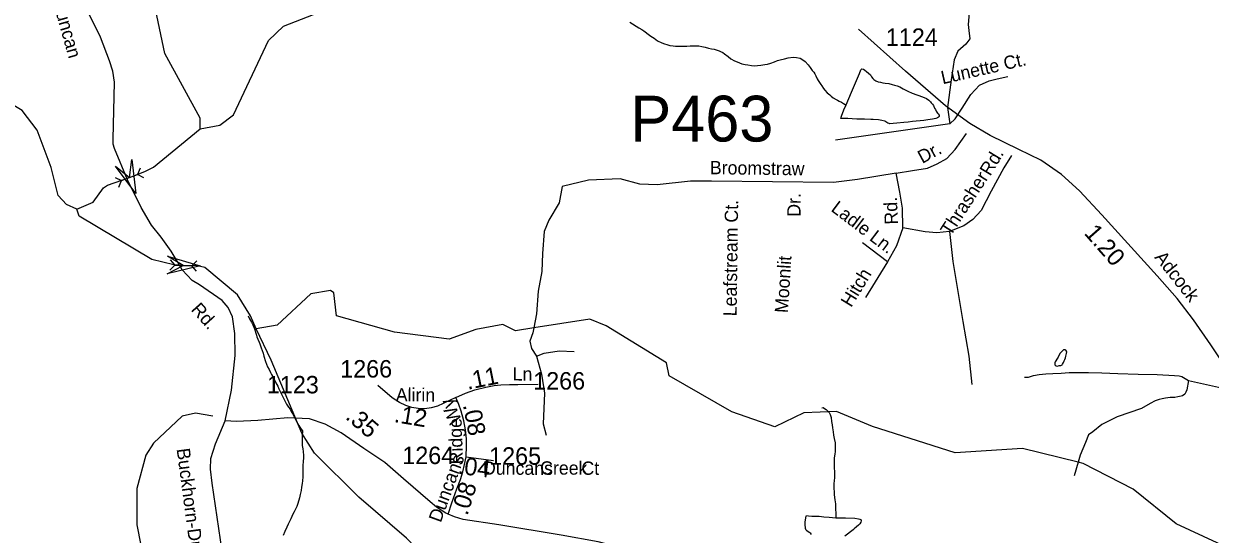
# Model space of a CAD drawing. Extents: x 2001466 to 2224147, y 644118 to 847247.
# Drawn here: x 2037525 to 2046028, y 669371 to 673026 of the extents above; entities that cross this region are included whole.
import ezdxf

# ---------------------------------------------------------------- set-up
doc = ezdxf.new("R2010")
doc.units = 0
for name, color, linetype in [('Exist Hydrographic Creek Single Shore', 7, 'Continuous'), ('Exist Hydrographic Misc Water Feature', 7, 'Continuous'), ('Exist Road Non-System Type 51', 7, 'Continuous'), ('Exist Road Non-System Type 51 Label', 7, 'Continuous'), ('Exist Road Secondary Mileage Hundredths English Label', 7, 'Continuous'), ('Exist Road Secondary Structure Pipe Attributed CELL', 7, 'Continuous'), ('Exist Road Secondary Structure Pipe CELL', 7, 'Continuous'), ('Exist Road Secondary Structure Pipe Number Label', 7, 'Continuous'), ('Exist Road Secondary Type 51 Attributed', 7, 'Continuous'), ('Exist Road Secondary Type 51 Label', 7, 'Continuous'), ('Exist Road Secondary Type 51 Number Label', 7, 'Continuous')]:
    doc.layers.add(name, color=color, linetype=linetype)

msp = doc.modelspace()

# ---------------------------------------------------------------- linework, layer by layer
at = {"layer": 'Exist Hydrographic Creek Single Shore'}
for points in [[(2038788.6, 672274), (2038930.7, 672300.6), (2039029.5, 672374), (2039278.6, 672907.1), (2039387.5, 673009.9), (2039645.7, 673109.6), (2040194.6, 673236.3), (2040902.7, 673569.6), (2041035.5, 673711.3), (2041110.6, 673860.7), (2041617.7, 674513.2), (2041766.5, 674605.3), (2042058.7, 674697.8), (2042616.7, 674673.3)], [(2037906.6, 671698), (2037831.6, 671732.4), (2037772.5, 671795.9), (2037722.5, 671997.1), (2037622.6, 672264.9), (2037513.6, 672404.9), (2037430.5, 672455.7), (2037236.1, 672453.3)], [(2037906.6, 671698), (2038022.5, 671748.2), (2038097, 671850.7), (2038125.6, 671871.2), (2038283.2, 671924.9), (2038393.2, 671968.8), (2038456.2, 671998.9), (2038788.6, 672274)], [(2039190.5, 670841.9), (2039149.5, 670934.6), (2039057.6, 671084.1), (2038823.4, 671280.8), (2038769.9, 671291.8), (2038668.7, 671295.5), (2038600.6, 671299.2), (2038444.5, 671338.8), (2037923.7, 671648.5), (2037906.6, 671698)]]:
    msp.add_lwpolyline(points, dxfattribs=at)
at = {"layer": 'Exist Hydrographic Misc Water Feature'}
for points in [[(2038788.6, 672274), (2038788.6, 672349.4), (2038537.6, 672813.9), (2038470.5, 673130.2), (2038211.6, 673388.1), (2038211.6, 673463.6), (2038027.6, 673723.2), (2038043.1, 674053.8)], [(2041868, 673038.1), (2041887.9, 673026.2), (2041914, 673010.2), (2041933.9, 672998.3), (2041954.2, 672986.3), (2041968.1, 672976.3), (2041978.2, 672968.3), (2042000.1, 672952.4), (2042020, 672938.4), (2042042.1, 672922.4), (2042068.2, 672904.5), (2042098.1, 672890.6), (2042116.2, 672882.6), (2042134.2, 672876.6), (2042156.1, 672870.7), (2042178.3, 672868.7), (2042196.1, 672866.7), (2042212.1, 672864.8), (2042232.2, 672864.8), (2042256.2, 672866.9), (2042276.3, 672866.9), (2042300.3, 672868.9), (2042332.3, 672869), (2042362.2, 672867.1), (2042384.2, 672863.1), (2042408.2, 672859.1), (2042432.1, 672851.2), (2042454.3, 672847.2), (2042474.2, 672843.2), (2042488.1, 672839.3), (2042508.2, 672831.3), (2042518.3, 672827.4), (2042536.1, 672819.4), (2042546.2, 672811.5), (2042572.4, 672791.4), (2042592.3, 672775.5), (2042618.3, 672761.6), (2042638.4, 672753.6), (2042672.3, 672739.6), (2042694.4, 672735.7), (2042714.3, 672731.7), (2042740.3, 672727.8), (2042760.2, 672725.8), (2042784.4, 672727.9), (2042808.4, 672730), (2042836.3, 672734), (2042854.3, 672736), (2042878.3, 672744.1), (2042904.4, 672754.1), (2042926.3, 672762.1), (2042946.2, 672768.1), (2042976.1, 672776.2), (2043004.2, 672782.2), (2043038.3, 672786.3)], [(2043038.3, 672786.3), (2043064.1, 672784.4), (2043090.2, 672780.4), (2043108.2, 672768.5), (2043126.2, 672756.5), (2043146.3, 672732.5), (2043160.3, 672712.6), (2043174.2, 672692.6), (2043186.3, 672678.6), (2043194.5, 672666.6), (2043202.5, 672652.6), (2043212.4, 672632.7), (2043218.5, 672620.7), (2043228.4, 672606.7), (2043238.6, 672590.8), (2043244.6, 672580.8), (2043256.7, 672562.8), (2043266.5, 672550.8), (2043282.5, 672532.8), (2043292.7, 672524.9), (2043302.6, 672516.9), (2043312.6, 672506.9), (2043326.8, 672496.9), (2043346.7, 672485), (2043356.7, 672479), (2043368.6, 672473), (2043384.6, 672465), (2043400.6, 672455.1), (2043412.9, 672449.1), (2043418.9, 672445.1)], [(2043418.9, 672445.1), (2043456.6, 672537.2), (2043514.4, 672669.2), (2043524.3, 672695.3), (2043532.2, 672703.3), (2043542.3, 672701.3), (2043552.3, 672693.4), (2043564.2, 672683.4), (2043578.4, 672671.4), (2043592.3, 672659.4), (2043600.3, 672647.4), (2043610.4, 672635.4), (2043618.4, 672627.5), (2043632.5, 672617.5), (2043648.5, 672611.5), (2043664.5, 672607.5), (2043682.3, 672603.6), (2043698.3, 672601.6), (2043724.4, 672597.6), (2043748.4, 672591.7), (2043766.4, 672587.7), (2043784.5, 672581.8), (2043802.5, 672573.8), (2043828.3, 672559.9), (2043860.5, 672543.9), (2043892.5, 672530), (2043924.5, 672518), (2043940.5, 672512), (2043958.6, 672506.1), (2043978.6, 672498.1), (2043994.6, 672490.1), (2044010.6, 672480.2), (2044022.5, 672468.2), (2044028.7, 672460.2), (2044038.7, 672450.3), (2044044.7, 672440.3), (2044052.7, 672422.3), (2044058.6, 672412.3), (2044064.8, 672400.3), (2044072.8, 672386.3), (2044078.7, 672380.3), (2044084.9, 672372.3), (2044084.9, 672362.3), (2044080.8, 672358.3), (2044072.8, 672352.4), (2044060.9, 672348.3), (2044038.7, 672344.3), (2044004.9, 672338.2), (2043974.8, 672334.2), (2043895, 672326.1), (2043863, 672322), (2043832.9, 672319.9), (2043781, 672313.8), (2043754.9, 672311.8), (2043733, 672309.7), (2043726.8, 672311.7), (2043718.8, 672315.6), (2043696.9, 672327.6), (2043675, 672333.6), (2043651, 672337.5), (2043612.8, 672341.5), (2043596.8, 672341.5), (2043550.9, 672343.3), (2043531, 672343.3), (2043494.9, 672343.3), (2043460.9, 672345.2), (2043431, 672347.2), (2043412.9, 672347.1), (2043394.9, 672347.1), (2043380.9, 672347), (2043385, 672365), (2043402.9, 672409.1), (2043418.9, 672445.1)], [(2041180.7, 670847.9), (2041049.5, 670827.1), (2040957.6, 670871.6), (2040765.5, 670836.1), (2040574.6, 670767.9), (2040182.5, 670818.5), (2039765.6, 670935.2), (2039748.6, 671099.6), (2039723.6, 671116.5), (2039582.5, 671093.1), (2039340.6, 670868.4), (2039190.5, 670841.9)], [(2039134.3, 670935.4), (2039144.3, 670913.3), (2039158.3, 670889.4), (2039166.5, 670871.4), (2039174.5, 670853.5), (2039182.5, 670835.5), (2039188.4, 670811.5), (2039192.5, 670795.5), (2039196.6, 670783.5), (2039202.6, 670767.6), (2039212.6, 670745.6), (2039216.7, 670733.6), (2039226.8, 670705.6), (2039234.8, 670687.6), (2039240.7, 670667.6), (2039246.9, 670645.6), (2039258.8, 670607.7), (2039264.9, 670589.7), (2039272.9, 670569.7), (2039283, 670549.7), (2039293, 670529.7), (2039301, 670513.8), (2039314.9, 670489.8), (2039322.9, 670475.8), (2039333, 670455.8), (2039345.1, 670431.9), (2039353.1, 670411.9), (2039365.2, 670387.8), (2039375.2, 670368), (2039385.3, 670349.9), (2039409.5, 670302), (2039423.4, 670280), (2039433.5, 670266), (2039445.4, 670246.1), (2039453.6, 670232.1), (2039475.5, 670188.1), (2039495.6, 670150.2), (2039503.6, 670138.2), (2039513.6, 670122.2), (2039523.7, 670110.3)], [(2045081.2, 669887), (2044683.4, 669985.5), (2044200.5, 669952.7), (2043608.5, 670141.9), (2043349.5, 670248.8), (2043116.4, 670240.5), (2042908.5, 670139.7), (2042599.5, 670247.7), (2042149.6, 670506.2), (2042132.6, 670598.4), (2041698.5, 670863.1), (2041582.6, 670911.4), (2041180.7, 670847.9)], [(2041120.4, 668328.9), (2040778.4, 668654), (2040469.6, 669136.1), (2040268.4, 669343.6), (2039926.6, 669635.9), (2039609.6, 669950.8), (2039517.5, 670093.8), (2039299.6, 670616.5), (2039190.5, 670841.9)], [(2044937.7, 670638.3), (2044929.7, 670624.2), (2044921.7, 670612.2), (2044917.8, 670606.2), (2044913.9, 670598.2), (2044913.9, 670592.2), (2044913.9, 670586.2), (2044915.9, 670582.2), (2044923.9, 670576.2), (2044933.8, 670574.2), (2044945.9, 670578.2), (2044957.8, 670580.3), (2044966, 670584.3), (2044969.9, 670588.3), (2044975.8, 670600.3), (2044981.8, 670612.3), (2044985.7, 670622.4), (2044989.8, 670634.4), (2044993.7, 670646.4), (2044995.7, 670656.4), (2044997.8, 670664.4), (2044999.6, 670676.4), (2044997.6, 670682.4), (2044993.7, 670688.4), (2044989.6, 670692.3), (2044981.6, 670692.3), (2044975.6, 670690.3), (2044969.7, 670684.3), (2044963.7, 670680.3), (2044949.8, 670664.3), (2044937.7, 670638.3)], [(2043244.8, 670277.2), (2043254.5, 670278.1), (2043264.7, 670271.2), (2043276.8, 670263.2), (2043286.8, 670253.2), (2043296.8, 670243.3), (2043304.8, 670227.3), (2043310.8, 670207.2), (2043314.9, 670179.3), (2043318.8, 670155.3), (2043321, 670133.3), (2043324.9, 670105.3), (2043329, 670079.3), (2043333.1, 670055.4), (2043339.1, 670025.4), (2043339.3, 670005.4), (2043339.3, 669963.4), (2043337.4, 669945.4), (2043333.3, 669917.4), (2043333.3, 669891.4), (2043333.6, 669865.4), (2043333.6, 669841.4), (2043335.4, 669823.4), (2043335.6, 669801.4), (2043335.6, 669777.4), (2043333.6, 669753.4), (2043331.7, 669735.4), (2043331.7, 669719.4), (2043331.7, 669699.4), (2043331.9, 669673.4), (2043333.8, 669655.5), (2043335.8, 669633.5), (2043337.9, 669617.5), (2043342, 669589.5), (2043342, 669571.5), (2043342, 669551.4), (2043344, 669521.5), (2043346.1, 669503.5), (2043346.1, 669489.5)], [(2039523.7, 670110.3), (2039519.8, 670072.3), (2039519.8, 670048.2), (2039520, 670026.2), (2039521.8, 670006.2), (2039523.9, 669994.3), (2039525.9, 669982.3), (2039528, 669964.3), (2039530, 669934.3), (2039530, 669920.3), (2039528.2, 669888.3), (2039526.1, 669866.3), (2039526.1, 669850.3), (2039526.1, 669838.3), (2039526.4, 669820.3), (2039526.4, 669800.3), (2039524.3, 669782.3), (2039522.5, 669754.3), (2039520.4, 669734.3), (2039516.3, 669708.3), (2039512.6, 669684.3), (2039506.5, 669654.3), (2039500.5, 669632.2), (2039496.6, 669614.2), (2039486.6, 669584.2), (2039482.7, 669570.3), (2039474.7, 669554.3), (2039462.8, 669530.3), (2039454.8, 669514.2), (2039438.8, 669480.2), (2039430.8, 669462.2), (2039421, 669442.2), (2039410.9, 669422.1), (2039397, 669390.1), (2039385.1, 669362.1)], [(2046476.4, 668863.1), (2046176.4, 669262.9), (2045784.5, 669444.8), (2045475.5, 669693.8), (2045116.5, 669878.3), (2045081.2, 669887)], [(2043170.3, 669369.2), (2043166.4, 669375.1), (2043158.4, 669381.1), (2043146.3, 669389.1), (2043138.3, 669395.1), (2043132.4, 669401.1), (2043128.3, 669411.1), (2043126.5, 669421.1), (2043124.2, 669433.1), (2043124.2, 669445.1), (2043126.2, 669459.1), (2043128.3, 669471.1), (2043130.1, 669489.1), (2043132.2, 669501.1), (2043134, 669505.1), (2043150, 669503.2), (2043172.2, 669501.2), (2043200.1, 669501.2), (2043226.1, 669499.3), (2043258.1, 669495.4), (2043298.1, 669493.4), (2043346.1, 669489.5)], [(2043346.1, 669489.5), (2043386, 669487.6), (2043414.1, 669487.6), (2043480.2, 669485.7), (2043508.1, 669481.8), (2043518.1, 669479.8), (2043526.1, 669473.8), (2043526.1, 669467.8), (2043524, 669457.8), (2043516.3, 669445.8), (2043508.3, 669435.8), (2043492.3, 669423.8), (2043476.3, 669409.7), (2043468.3, 669401.7), (2043450.4, 669387.7), (2043428.3, 669371.7), (2043408.4, 669357.7)]]:
    msp.add_lwpolyline(points, dxfattribs=at)
at = {"layer": 'Exist Road Non-System Type 51'}
for p, q in [((2044161.3, 672309.9), (2043342.9, 672192.5)), ((2043714.6, 671321.8), (2043536.4, 671456.8)), ((2043714.6, 671321.8), (2043558, 671065.2)), ((2045871.9, 670471.2), (2046173, 670406.1)), ((2045081.2, 669887), (2045052.5, 669790.2))]:
    msp.add_line(p, q, dxfattribs=at)
for points in [[(2044319.9, 673656.2), (2044312, 673281.1), (2044304.1, 673163.5), (2044298.8, 673076.4), (2044293.5, 673020.9), (2044298.8, 672978.6), (2044304.1, 672917.9), (2044277.7, 672880.9), (2044219.6, 672830.7), (2044193.2, 672767.3), (2044172.1, 672624.7), (2044145.7, 672426.6), (2044161.3, 672309.9)], [(2044161.3, 672309.9), (2044201.1, 672346), (2044251.3, 672422.6), (2044312, 672520.4), (2044375.4, 672586.4), (2044444, 672618.1), (2044502.1, 672631.3), (2044578.7, 672649.8)], [(2043776.7, 671956.6), (2043895.5, 671975.5), (2044000.8, 671991.7), (2044071, 672024.1), (2044141.2, 672061.9), (2044200.6, 672126.7), (2044282.1, 672240.4)], [(2044602.9, 672083.5), (2044548.9, 671994.4), (2044457.1, 671826.9), (2044386.9, 671689.1), (2044327.5, 671624.3), (2044262.7, 671578.4), (2044160.1, 671537.9)], [(2043776.7, 671956.6), (2043501.3, 671910.6), (2043328.5, 671889), (2042453.7, 671899.8), (2042302.5, 671899.8), (2042064.9, 671872.8), (2041940.7, 671878.2), (2041800.3, 671916), (2041573.5, 671905.2), (2041384.5, 671862), (2041362.9, 671743.2), (2041287.3, 671618.9), (2041254.9, 671537.9), (2041244.1, 671381.2), (2041238.7, 671251.5), (2041211.7, 671111.1), (2041200.9, 670949), (2041180.7, 670847.9)], [(2043825.3, 671564.9), (2043822.6, 671705.3), (2043803.7, 671821.5), (2043776.7, 671956.6)], [(2043825.3, 671564.9), (2043779.4, 671435.2), (2043714.6, 671321.8)], [(2044160.1, 671537.9), (2044068.3, 671529.8), (2043984.6, 671535.2), (2043825.3, 671564.9)], [(2044160.1, 671537.9), (2044184.4, 671324.5), (2044254.6, 670895), (2044297.8, 670646.5), (2044319.4, 670443.9)], [(2041180.7, 670847.9), (2041173.9, 670813.9), (2041152.3, 670754.5), (2041163.1, 670700.5), (2041200.9, 670646.5)], [(2041200.9, 670646.5), (2041254.9, 670668.1), (2041362.9, 670684.3), (2041470.9, 670678.9)], [(2041200.9, 670646.5), (2041236, 670516.8), (2041257.6, 670381.8), (2041246.8, 670160.3), (2041268.4, 670079.2)], [(2044696.4, 670495), (2044710.4, 670494.8), (2044726.4, 670496.4), (2044760.6, 670507.7), (2044802.8, 670514.9), (2044848.9, 670520), (2044898.9, 670520.9), (2044959, 670523.7), (2045017.1, 670528.5), (2045061.1, 670529.6), (2045155.1, 670529.7), (2045251, 670525.8), (2045366.9, 670521.4), (2045510.8, 670516.5), (2045648.8, 670513.7), (2045772.6, 670507.2), (2045804.6, 670504.5), (2045824.5, 670500.1), (2045871.9, 670471.2)], [(2045871.9, 670471.2), (2045860.6, 670405.4), (2045854.2, 670387.5), (2045845.9, 670373.7), (2045829.7, 670362), (2045819.6, 670360.2), (2045795.5, 670354.7), (2045773.5, 670351.2), (2045741.4, 670349.8), (2045707.3, 670344.5), (2045683.2, 670341), (2045663.1, 670335.4), (2045632.9, 670326), (2045598.5, 670306.7), (2045535.8, 670272), (2045360.3, 670211.6), (2045252.3, 670157.5), (2045187.5, 670103.5), (2045155.1, 670081.9), (2045133.5, 670027.9), (2045095.7, 669936.1), (2045081.2, 669887)], [(2038881.6, 670217), (2038757.4, 670238.6), (2038660.2, 670217), (2038454.9, 670022.5), (2038400.9, 669936), (2038336.1, 669698.3), (2038336.1, 669439), (2038390.1, 669158.1), (2038428.2, 668960.1)]]:
    msp.add_lwpolyline(points, dxfattribs=at)
at = {"layer": 'Exist Road Secondary Structure Pipe Attributed CELL'}
for points in [[(2038298.9, 672053.9), (2038329.2, 671812), (2038181.9, 672006.4), (2038283.2, 671924.9)], [(2038556.5, 671361.1), (2038790.6, 671292.8), (2038553.8, 671234.9), (2038668.7, 671295.5)]]:
    msp.add_lwpolyline(points, close=True, dxfattribs=at)
at = {"layer": 'Exist Road Secondary Structure Pipe CELL'}
for p, q in [((2038359.5, 671993), (2038339.8, 671946.2)), ((2038181, 671925.8), (2038226.6, 671903.6)), ((2038206.9, 671856.8), (2038226.6, 671903.6)), ((2038226.6, 671903.6), (2038339.8, 671946.2)), ((2038385.5, 671924), (2038339.8, 671946.2)), ((2038575, 671336.3), (2038608.3, 671298)), ((2038765.5, 671328.4), (2038729.1, 671293)), ((2038571.9, 671262.6), (2038608.3, 671298)), ((2038608.3, 671298), (2038729.1, 671293)), ((2038762.5, 671254.7), (2038729.1, 671293))]:
    msp.add_line(p, q, dxfattribs=at)
at = {"layer": 'Exist Road Secondary Type 51 Attributed'}
msp.add_line((2040695.5, 669924.3), (2040892.1, 669900), dxfattribs=at)
for points in [[(2038968.1, 670183.9), (2039014.1, 670403.3), (2039040.5, 670651.7), (2039037.1, 670807.5), (2039020.5, 670926.8), (2038991.2, 670994.7), (2038947.4, 671045.4), (2038784.1, 671157), (2038732.7, 671188.2), (2038659.6, 671263.1), (2038624.7, 671325.5), (2038582.2, 671398.1), (2038510.4, 671497.2), (2038442, 671585.1), (2038367.7, 671709.6), (2038268.7, 671907.9), (2038174.7, 672133.9), (2038165.1, 672164.5), (2038165.3, 672199.3), (2038176.2, 672607.7), (2038163.6, 672685.9), (2038140.1, 672761.9), (2038075.8, 672930.3), (2037992.6, 673099.8)], [(2048069.1, 669827.3), (2047827.8, 669845.2), (2047566, 669864.2), (2047497.9, 669887.4), (2047112.6, 670048), (2046612.3, 670260.3), (2046306.7, 670400.8), (2046240.2, 670447.3), (2046147.3, 670556.1), (2046032.2, 670726.2), (2045908.2, 670906.8), (2045789.9, 671058.9), (2045648.5, 671221.6), (2045252.1, 671658.9), (2045091.1, 671829), (2044962.4, 671947.3), (2044813.5, 672048.7), (2044655.2, 672125.8), (2044452, 672227.2), (2044304.2, 672311.7), (2044131.1, 672439.5), (2043843.4, 672687.8), (2043508.3, 672986.7)], [(2040621.5, 670350.5), (2040580.8, 670330.8), (2040532.1, 670306.5), (2040490.9, 670287.8), (2040446, 670275.6), (2040398.7, 670269), (2040351.9, 670270.9), (2040307, 670278.4), (2040263, 670293.4), (2040219, 670313.1), (2040165.6, 670346.8), (2040063.9, 670435.8)], [(2040621.5, 670350.5), (2040690.8, 670380.5), (2040759.1, 670405.8), (2040836.4, 670423.6), (2040897.2, 670435.8), (2040945, 670441.4), (2041006.7, 670443.2), (2041066.7, 670444.2), (2041210.8, 670445.1)], [(2040695.5, 669924.3), (2040697.3, 670004.9), (2040697.3, 670053.6), (2040690.8, 670119.2), (2040678.6, 670183.8), (2040659, 670252.2), (2040644, 670299), (2040621.5, 670350.5)], [(2040561, 669517.6), (2040551.2, 669522.1), (2040483, 669565.6), (2040438.1, 669603.3), (2040248, 669768.1), (2040112.9, 669884.3), (2039963, 669985.7), (2039799.4, 670097.6), (2039685.4, 670158.9), (2039573.5, 670196.9), (2039417.3, 670203.3), (2039204.1, 670184.3), (2039050.5, 670177.9), (2038968.1, 670183.9)], [(2039941.9, 666139.6), (2039888.1, 666231.5), (2039829, 666337.1), (2039782.5, 666408.9), (2039719.2, 666491.3), (2039557.1, 666659.3), (2039371.4, 666881.1), (2039289.5, 666994.1), (2039248.4, 667061.7), (2039195.6, 667225.5), (2039104.8, 667545.5), (2039079.5, 667666), (2039064.7, 667794.8), (2039069.5, 668028.3), (2039054.7, 668367.4), (2039027.8, 668703.3), (2038995, 668984.3), (2038946.5, 669250.5), (2038875.7, 669736.4), (2038863.1, 669837.8), (2038867.3, 669913.8), (2038899, 670017.4), (2038968.1, 670183.9)], [(2040566.4, 669515.2), (2040592.5, 669596.5), (2040629, 669696.7), (2040654.3, 669763.2), (2040671.1, 669816.6), (2040683.3, 669870), (2040695.5, 669924.3)], [(2047420.9, 668051.6), (2046969, 668061), (2046413.8, 668075.8), (2046167.8, 668094.8), (2045802.6, 668154), (2045268.5, 668253.3), (2045058.4, 668308.2), (2044644.6, 668454), (2044002.8, 668665.3), (2043102.4, 668923), (2042428.9, 669113.1), (2041642.5, 669316), (2041375.5, 669363.9), (2040930.6, 669438.5), (2040675.4, 669476.9), (2040612.2, 669494.4), (2040566.4, 669515.2)]]:
    msp.add_lwpolyline(points, dxfattribs=at)

# ---------------------------------------------------------------- texts
at = {"layer": 'Exist Road Non-System Type 51 Label'}
for s, rotation, p in [('Lunette Ct.', 12.80947, (2044110.6, 672592.7)), ('Dr.', 28.31145, (2043964.1, 672022.4)), ('Rd.', 58.79304, (2044450.8, 671930.5)), ('Broomstraw', 359.29233, (2042441.9, 671949.2)), ('Thrasher', 57.11073, (2044167.4, 671500.4)), ('Leafstream Ct.', 89.18831, (2042633.6, 670931.1)), ('Dr.', 89.51054, (2043091.8, 671644)), ('Ladle Ln.', 322.84124, (2043303.9, 671689.9)), ('Rd.', 92.34692, (2043790.7, 671590.4)), ('Moonlit', 86.42515, (2043001.6, 670953.1)), ('Hitch', 58.60612, (2043454.6, 670990.1))]:
    msp.add_text(s, height=95, rotation=rotation, dxfattribs=at).set_placement(p)
at = {"layer": 'Exist Road Secondary Mileage Hundredths English Label'}
for s, rotation, p in [('1.20', 311.34556, (2045119.1, 671523.8)), ('.11', 11.31604, (2040706.8, 670404.9)), ('.08', 280.66388, (2040672.5, 670296.2)), ('.35', 319.30551, (2039824.6, 670202.4)), ('.12', 350.53244, (2040174.6, 670174.6)), ('.04', 352.93853, (2040630.9, 669804.4)), ('.08', 72.48275, (2040704, 669499.4))]:
    msp.add_text(s, height=125, rotation=rotation, dxfattribs=at).set_placement(p)
at = {"layer": 'Exist Road Secondary Structure Pipe Number Label'}
msp.add_text('P463', height=328.08, dxfattribs=at).set_placement((2041872.9, 672183))
at = {"layer": 'Exist Road Secondary Type 51 Label'}
for s, rotation, p in [('Buckhorn-Duncan', 285.84613, (2037571.4, 673749.8)), ('Adcock', 308.35323, (2045624.5, 671352.2)), ('Rd.', 311.975, (2038719, 670976.2)), ('Ln', 359.83395, (2041028.8, 670471.9)), ('Alirin', 359.83395, (2040191.5, 670322)), ('Wy', 113.35528, (2040666.6, 670185.5)), ('Ridge', 92.0076, (2040674.1, 669872.6)), ('Buckhorn-Duncan', 277.57345, (2038620.6, 669981.2)), ('Duncans', 70.01139, (2040513.5, 669449.5)), ('Duncans', 359.83395, (2040816.3, 669797.3)), ('Creek', 359.83395, (2041226.1, 669798.2)), ('Ct', 359.83395, (2041521.8, 669796.6))]:
    msp.add_text(s, height=95, rotation=rotation, dxfattribs=at).set_placement(p)
at = {"layer": 'Exist Road Secondary Type 51 Number Label'}
for s, p in [('1124', (2043703.6, 672867.9)), ('1266', (2039793.5, 670493)), ('1123', (2039268.1, 670379.5)), ('1266', (2041176.5, 670406.7)), ('1264', (2040238.2, 669873.1)), ('1265', (2040860.9, 669868.6))]:
    msp.add_text(s, height=125, dxfattribs=at).set_placement(p)

doc.saveas('drawing.dxf')
